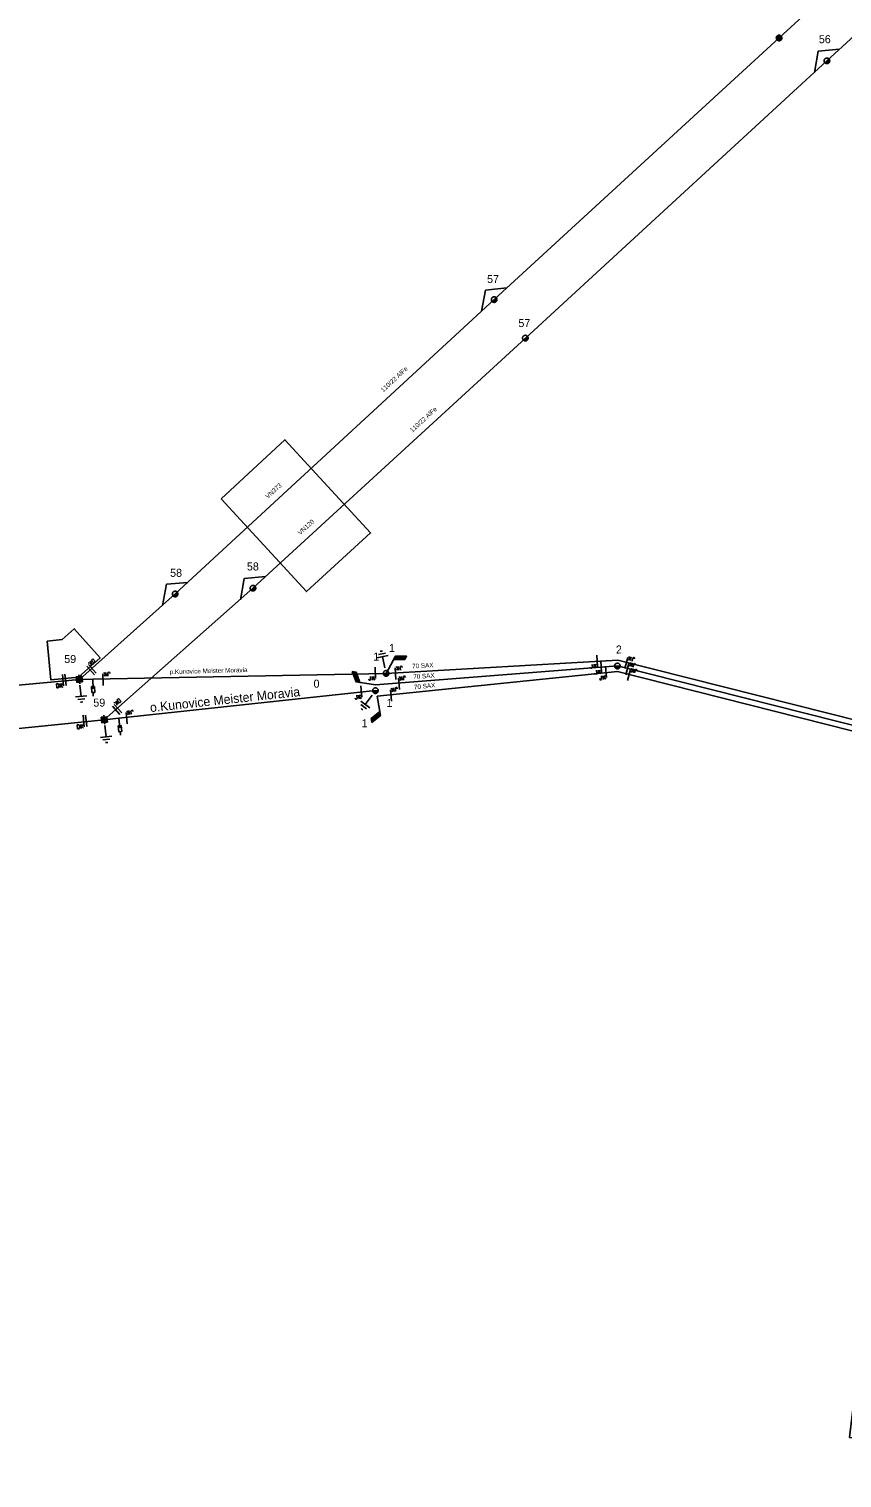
# Model space of a CAD drawing. Extents: x -540340 to -537226, y -1183949 to -1180375.
# Drawn here: x -539921.3 to -539743.5, y -1183378.3 to -1183061.3 of the extents above; entities that cross this region are included whole.
import ezdxf

# ---------------------------------------------------------------- set-up
doc = ezdxf.new("R2010")
doc.units = 0
for name, color, linetype in [('Default', 7, 'Continuous'), ('Vrstva 1', 7, 'Continuous'), ('Vrstva 11', 7, 'Continuous'), ('Vrstva 12', 7, 'Continuous'), ('Vrstva 13', 7, 'Continuous'), ('Vrstva 14', 7, 'Continuous'), ('Vrstva 15', 7, 'Continuous'), ('Vrstva 16', 7, 'Continuous'), ('Vrstva 18', 7, 'Continuous'), ('Vrstva 2', 7, 'Continuous'), ('Vrstva 3', 7, 'Continuous'), ('Vrstva 35', 7, 'Continuous'), ('Vrstva 4', 7, 'Continuous'), ('Vrstva 52', 7, 'Continuous'), ('Vrstva 54', 7, 'Continuous'), ('Vrstva 57', 7, 'Continuous'), ('Vrstva 59', 7, 'Continuous')]:
    doc.layers.add(name, color=color, linetype=linetype)

# ---------------------------------------------------------------- blocks, each defined once
blk = doc.blocks.new('VN850')
at = {"layer": 'Vrstva 15'}
for points in [[(-0.56, 1.43), (-0.56, -1.07)], [(-0.01, 1.43), (-0.01, -1.07)], [(-2.09, -0.54), (-1.78, -0.54)], [(-2.09, -1.41), (-2.09, -0.54)], [(-1.78, -1.41), (-2.09, -1.41)], [(-1.78, -0.54), (-1.66, -0.6)], [(-1.67, -1.35), (-1.78, -1.41)], [(-1.59, -1.2), (-1.67, -1.35)], [(-1.66, -0.6), (-1.59, -0.75)], [(-1.59, -0.75), (-1.55, -0.96)], [(-1.55, -0.96), (-1.59, -1.2)], [(-1.26, -0.54), (-1.26, -1.41)], [(-0.85, -0.54), (-1.26, -1.09)], [(-1.13, -0.92), (-0.77, -1.41)]]:
    blk.add_lwpolyline(points, dxfattribs=at)
blk = doc.blocks.new('VN840')
at = {"layer": 'Vrstva 15'}
for points in [[(-0.01, 1.41), (-0.01, -1.09)], [(-1.51, -1.24), (-1.51, -1.15)], [(-1.48, -1.35), (-1.51, -1.24)], [(-1.33, -1.42), (-1.48, -1.35)], [(-1.27, -1.42), (-1.33, -1.42)], [(-1.13, -1.35), (-1.27, -1.42)], [(-1.09, -1.24), (-1.13, -1.35)], [(-1.09, -0.59), (-1.09, -1.24)], [(-0.68, -0.59), (-0.68, -1.42)], [(-0.68, -1.11), (-0.27, -0.59)], [(-0.54, -0.94), (-0.2, -1.42)]]:
    blk.add_lwpolyline(points, dxfattribs=at)
blk = doc.blocks.new('VN860')
at = {"layer": 'Vrstva 15'}
for points in [[(-3.74, 0), (0.01, 2.82)], [(0.01, 2.82), (3.76, 0)]]:
    blk.add_lwpolyline(points, dxfattribs=at)
blk = doc.blocks.new('VN440')
at = {"layer": 'Vrstva 2'}
for points in [[(1.22, 0), (1.21, 0.13), (1.19, 0.25), (1.16, 0.38), (1.11, 0.5), (1.05, 0.61), (0.98, 0.72), (0.9, 0.82), (0.81, 0.91), (0.71, 0.99), (0.6, 1.06), (0.49, 1.12), (0.37, 1.16), (0.25, 1.2), (0.12, 1.22), (-0.01, 1.22), (-0.14, 1.22), (-0.26, 1.2), (-0.39, 1.16), (-0.51, 1.12), (-0.62, 1.06), (-0.73, 0.99), (-0.83, 0.91), (-0.92, 0.82), (-1, 0.72), (-1.07, 0.61), (-1.13, 0.5), (-1.18, 0.38), (-1.21, 0.25), (-1.23, 0.13), (-1.24, 0), (-1.23, -0.13), (-1.21, -0.26), (-1.18, -0.38), (-1.13, -0.5), (-1.07, -0.62), (-1, -0.73), (-0.92, -0.83), (-0.83, -0.92), (-0.73, -1), (-0.62, -1.07), (-0.51, -1.13), (-0.39, -1.17), (-0.26, -1.2), (-0.14, -1.23), (-0.01, -1.23), (0.12, -1.23), (0.25, -1.2), (0.37, -1.17), (0.49, -1.13), (0.6, -1.07), (0.71, -1), (0.81, -0.92), (0.9, -0.83), (0.98, -0.73), (1.05, -0.62), (1.11, -0.5), (1.16, -0.38), (1.19, -0.26), (1.21, -0.13), (1.22, 0)], [(-1.24, 0), (1.22, 0)], [(-1.18, -0.34), (1.1, -0.34)], [(-1.01, -0.63), (0.97, -0.63)], [(-0.74, -0.92), (0.68, -0.92)]]:
    blk.add_lwpolyline(points, dxfattribs=at)
blk = doc.blocks.new('VN820')
at = {"layer": 'Vrstva 13'}
for points in [[(0, 0), (0, -2.1)], [(-0.32, -1.63), (0.34, -1.63)], [(-0.32, -2.95), (-0.32, -1.63)], [(0.34, -2.95), (-0.32, -2.95)], [(0, -2.1), (-0.12, -1.86)], [(0, -2.1), (0.12, -1.86)], [(0, -2.95), (0, -3.75)], [(0.34, -1.63), (0.34, -2.95)]]:
    blk.add_lwpolyline(points, dxfattribs=at)
blk = doc.blocks.new('VN810')
at = {"layer": 'Vrstva 14'}
for points in [[(0, -1.25), (0, -3.75)], [(1.25, -3.75), (-1.25, -3.75)], [(0.77, -4.37), (-0.8, -4.37)], [(0, -5), (-0.25, -5)], [(0.27, -5), (0, -5)]]:
    blk.add_lwpolyline(points, dxfattribs=at)
blk = doc.blocks.new('VN001')
at = {"layer": 'Default'}
for p, q in [((1.82, 3.18), (4.23, 3.18)), ((1.85, 3.23), (4.26, 3.23)), ((1.87, 3.28), (4.29, 3.28)), ((1.9, 3.33), (4.32, 3.33)), ((1.93, 3.38), (4.35, 3.38)), ((1.96, 3.43), (4.37, 3.43)), ((1.99, 3.48), (4.4, 3.48)), ((2.02, 3.53), (4.43, 3.53)), ((2.05, 3.58), (4.46, 3.58)), ((2.07, 3.63), (4.49, 3.63)), ((2.1, 3.68), (4.52, 3.68)), ((2.13, 3.73), (2.54, 3.73)), ((1.73, 3.03), (4.14, 3.03)), ((1.76, 3.08), (4.17, 3.08)), ((1.79, 3.13), (4.2, 3.13))]:
    blk.add_line(p, q, dxfattribs=at)
blk.add_lwpolyline([(2.13, 3.73), (0, 0)], dxfattribs=at)
blk.add_lwpolyline([(4.55, 3.73), (2.13, 3.73), (1.7, 2.98), (4.12, 2.99)], close=True, dxfattribs=at)
blk = doc.blocks.new('VN460')
at = {"layer": 'Vrstva 2'}
for points in [[(1.23, 0), (1.22, 0.13), (1.2, 0.26), (1.17, 0.38), (1.12, 0.5), (1.06, 0.61), (0.99, 0.72), (0.91, 0.82), (0.82, 0.91), (0.72, 0.99), (0.61, 1.06), (0.5, 1.12), (0.38, 1.17), (0.26, 1.2), (0.13, 1.22), (0, 1.23), (-0.13, 1.22), (-0.26, 1.2), (-0.38, 1.17), (-0.5, 1.12), (-0.61, 1.06), (-0.72, 0.99), (-0.82, 0.91), (-0.91, 0.82), (-0.99, 0.72), (-1.06, 0.61), (-1.12, 0.5), (-1.17, 0.38), (-1.2, 0.26), (-1.22, 0.13), (-1.23, 0), (-1.22, -0.13), (-1.2, -0.26), (-1.17, -0.38), (-1.12, -0.5), (-1.06, -0.61), (-0.99, -0.72), (-0.91, -0.82), (-0.82, -0.91), (-0.72, -0.99), (-0.61, -1.06), (-0.5, -1.12), (-0.38, -1.17), (-0.26, -1.2), (-0.13, -1.22), (0, -1.23), (0.13, -1.22), (0.26, -1.2), (0.38, -1.17), (0.5, -1.12), (0.61, -1.06), (0.72, -0.99), (0.82, -0.91), (0.91, -0.82), (0.99, -0.72), (1.06, -0.61), (1.12, -0.5), (1.17, -0.38), (1.2, -0.26), (1.22, -0.13), (1.23, 0)], [(0.92, 0), (0.92, 0.1), (0.9, 0.19), (0.88, 0.28), (0.84, 0.37), (0.8, 0.46), (0.75, 0.54), (0.68, 0.62), (0.62, 0.68), (0.54, 0.74), (0.46, 0.8), (0.37, 0.84), (0.28, 0.88), (0.19, 0.9), (0.1, 0.92), (0, 0.92), (-0.1, 0.92), (-0.19, 0.9), (-0.28, 0.88), (-0.37, 0.84), (-0.46, 0.8), (-0.54, 0.74), (-0.62, 0.68), (-0.68, 0.62), (-0.75, 0.54), (-0.8, 0.46), (-0.84, 0.37), (-0.88, 0.28), (-0.9, 0.19), (-0.92, 0.1), (-0.92, 0), (-0.92, -0.1), (-0.9, -0.19), (-0.88, -0.29), (-0.84, -0.38), (-0.8, -0.46), (-0.75, -0.54), (-0.68, -0.62), (-0.62, -0.69), (-0.54, -0.75), (-0.46, -0.8), (-0.37, -0.84), (-0.28, -0.88), (-0.19, -0.9), (-0.1, -0.92), (0, -0.92), (0.1, -0.92), (0.19, -0.9), (0.28, -0.88), (0.37, -0.84), (0.46, -0.8), (0.54, -0.75), (0.62, -0.69), (0.68, -0.62), (0.75, -0.54), (0.8, -0.46), (0.84, -0.38), (0.88, -0.29), (0.9, -0.19), (0.92, -0.1), (0.92, 0)], [(0.61, 0), (0.61, 0.06), (0.6, 0.13), (0.58, 0.19), (0.56, 0.25), (0.53, 0.31), (0.5, 0.36), (0.46, 0.41), (0.41, 0.46), (0.36, 0.5), (0.31, 0.53), (0.25, 0.56), (0.19, 0.58), (0.13, 0.6), (0.06, 0.61), (0, 0.61), (-0.06, 0.61), (-0.13, 0.6), (-0.19, 0.58), (-0.25, 0.56), (-0.31, 0.53), (-0.36, 0.5), (-0.41, 0.46), (-0.46, 0.41), (-0.5, 0.36), (-0.53, 0.31), (-0.56, 0.25), (-0.58, 0.19), (-0.6, 0.13), (-0.61, 0.06), (-0.61, 0), (-0.61, -0.07), (-0.6, -0.13), (-0.58, -0.19), (-0.56, -0.25), (-0.53, -0.31), (-0.5, -0.36), (-0.46, -0.41), (-0.41, -0.46), (-0.36, -0.5), (-0.31, -0.53), (-0.25, -0.56), (-0.19, -0.58), (-0.13, -0.6), (-0.06, -0.61), (0, -0.61), (0.06, -0.61), (0.13, -0.6), (0.19, -0.58), (0.25, -0.56), (0.31, -0.53), (0.36, -0.5), (0.41, -0.46), (0.46, -0.41), (0.5, -0.36), (0.53, -0.31), (0.56, -0.25), (0.58, -0.19), (0.6, -0.13), (0.61, -0.06), (0.61, 0)], [(0.31, 0), (0.31, 0.03), (0.3, 0.06), (0.29, 0.09), (0.28, 0.12), (0.27, 0.15), (0.25, 0.18), (0.23, 0.21), (0.21, 0.23), (0.18, 0.25), (0.15, 0.27), (0.12, 0.28), (0.09, 0.29), (0.06, 0.3), (0.03, 0.31), (0, 0.31), (-0.03, 0.31), (-0.06, 0.3), (-0.09, 0.29), (-0.12, 0.28), (-0.15, 0.27), (-0.18, 0.25), (-0.21, 0.23), (-0.23, 0.21), (-0.25, 0.18), (-0.27, 0.15), (-0.28, 0.12), (-0.29, 0.09), (-0.3, 0.06), (-0.31, 0.03), (-0.31, 0), (-0.31, -0.03), (-0.3, -0.06), (-0.29, -0.1), (-0.28, -0.13), (-0.27, -0.15), (-0.25, -0.18), (-0.23, -0.21), (-0.21, -0.23), (-0.18, -0.25), (-0.15, -0.27), (-0.12, -0.28), (-0.09, -0.29), (-0.06, -0.3), (-0.03, -0.31), (0, -0.31), (0.03, -0.31), (0.06, -0.3), (0.09, -0.29), (0.12, -0.28), (0.15, -0.27), (0.18, -0.25), (0.21, -0.23), (0.23, -0.21), (0.25, -0.18), (0.27, -0.15), (0.28, -0.13), (0.29, -0.1), (0.3, -0.06), (0.31, -0.03), (0.31, 0)]]:
    blk.add_lwpolyline(points, dxfattribs=at)
blk = doc.blocks.new('VN470')
at = {"layer": 'Vrstva 2'}
for points in [[(-1.23, 1.22), (1.23, 1.22)], [(-1.23, -1.23), (-1.23, 1.22)], [(-0.92, 0.9), (0.92, 0.9)], [(-0.92, -0.95), (-0.92, 0.9)], [(-0.61, 0.61), (0.61, 0.61)], [(-0.61, -0.62), (-0.61, 0.61)], [(-0.31, -0.27), (-0.31, 0.34)], [(-0.31, 0.34), (0.31, 0.34)], [(0, 1.22), (0, 1.97)], [(0.31, 0.34), (0.31, -0.27)], [(0.61, 0.61), (0.61, -0.62)], [(0.92, 0.9), (0.92, -0.95)], [(1.23, 1.22), (1.23, -1.23)], [(1.23, -1.23), (-1.23, -1.23)], [(0.92, -0.95), (-0.92, -0.95)], [(0.61, -0.62), (-0.61, -0.62)], [(0.31, -0.27), (-0.31, -0.27)], [(0, -1.23), (0, -1.98)]]:
    blk.add_lwpolyline(points, dxfattribs=at)

msp = doc.modelspace()

# ---------------------------------------------------------------- linework, layer by layer
at = {"layer": 'Vrstva 1'}
for points in [[(-538750.53, -1181681.2), (-538749.33, -1181712.71), (-538744.97, -1181817.24), (-538743.58, -1181895.5), (-538773.54, -1181977.77), (-538805.22, -1182060.54), (-538837.47, -1182145.44), (-538866.82, -1182220.96), (-538895.79, -1182296.47), (-538969.65, -1182362.9), (-539051.89, -1182437.77), (-539124.04, -1182501.28), (-539198.82, -1182569.8), (-539277.47, -1182640.72), (-539357.09, -1182713.05), (-539436.34, -1182785.46), (-539516.79, -1182858.47), (-539596.04, -1182930.58), (-539682.18, -1183009.05), (-539746.81, -1183068.3), (-539812.77, -1183128.96), (-539872.34, -1183183.66), (-539904.86, -1183212.44)], [(-539910.31, -1183203.61), (-539889.36, -1183184.93), (-539819.58, -1183120.53), (-539757.27, -1183063.3), (-539687.65, -1182999.5), (-539602.47, -1182922.15), (-539522.85, -1182849.96), (-539443.45, -1182777.85), (-539363.3, -1182704.92), (-539283.21, -1182632.72)], [(-540012.36, -1183354.43), (-540009.96, -1183294.39), (-539986.67, -1183210.74), (-539910.31, -1183203.61)], [(-539904.86, -1183212.44), (-539980.4, -1183220.14), (-540003.99, -1183302.87), (-540008.15, -1183354.48)]]:
    msp.add_lwpolyline(points, dxfattribs=at)
at = {"layer": 'Vrstva 35'}
for points in [[(-539879.32, -1183164.09), (-539865.34, -1183151.2), (-539846.6, -1183171.57), (-539860.6, -1183184.42)], [(-539917.36, -1183195.23), (-539914.09, -1183194.92), (-539911.43, -1183192.55), (-539905.77, -1183198.89), (-539910.52, -1183203.13), (-539916.57, -1183203.69)]]:
    msp.add_lwpolyline(points, close=True, dxfattribs=at)
at = {"layer": 'Vrstva 4'}
for points in [[(-539843.22, -1183202.3), (-539792.51, -1183199.43), (-539723.81, -1183216.77), (-539658.93, -1183211.54), (-539583.06, -1183205.79)], [(-539910.31, -1183203.61), (-539907.36, -1183203.55), (-539843.22, -1183202.3)], [(-539845.55, -1183204.84), (-539792.63, -1183200.68), (-539723.91, -1183218), (-539734.07, -1183303.85), (-539741.84, -1183369.42), (-539668.89, -1183378.31)], [(-539845.19, -1183207.26), (-539792.58, -1183201.89), (-539724.05, -1183219.21), (-539658.75, -1183213.98), (-539582.95, -1183207.03)]]:
    msp.add_lwpolyline(points, dxfattribs=at)
at = {"layer": 'Vrstva 52'}
msp.add_lwpolyline([(-539904.86, -1183212.44), (-539901.69, -1183212.1), (-539845.55, -1183206.08)], dxfattribs=at)

# ---------------------------------------------------------------- block references
at = {"layer": 'Vrstva 11'}
for p, rotation in [((-539843.22, -1183202.3), 1.0974722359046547), ((-539845.55, -1183204.84), 110.73362780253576), ((-539845.19, -1183207.26), -140.40446383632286)]:
    msp.add_blockref('VN001', p, dxfattribs=dict(at, rotation=rotation))
at = {"layer": 'Vrstva 13'}
for name, p, xscale, yscale, rotation in [('VN460', (-539757.27, -1183063.31), 0.5, 0.5, 42.69776945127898), ('VN440', (-539746.81, -1183068.3), 0.5000000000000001, 0.5, 42.312650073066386), ('VN440', (-539819.58, -1183120.53), 0.5, 0.5, 42.39974992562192), ('VN440', (-539812.77, -1183128.96), 0.5, 0.5, 42.35340004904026), ('VN440', (-539889.36, -1183184.93), 0.5, 0.5, 41.722772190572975), ('VN440', (-539872.34, -1183183.66), 0.5, 0.5, 41.44218061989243), ('VN440', (-539792.63, -1183200.68), 0.5000000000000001, 0.5000000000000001, 1.8341054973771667), ('VN470', (-539910.31, -1183203.61), 0.49999999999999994, 0.5000000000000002, 5.629222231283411), ('VN440', (-539843.22, -1183202.3), 0.5000000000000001, 0.5, 1.0974722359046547), ('VN440', (-539845.55, -1183206.08), 0.4999999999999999, 0.49999999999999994, 5.99906389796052), ('VN470', (-539904.86, -1183212.45), 0.5000000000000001, 0.5, 5.814858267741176)]:
    msp.add_blockref(name, p, dxfattribs=dict(at, xscale=xscale, yscale=yscale, rotation=rotation))
at = {"layer": 'Vrstva 15'}
for p, rotation in [((-539843.22, -1183202.3), -168.0209639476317), ((-539910.31, -1183203.61), 5.629222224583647), ((-539845.55, -1183206.08), -36.26562504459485), ((-539904.86, -1183212.44), 5.814858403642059)]:
    msp.add_blockref('VN810', p, dxfattribs=dict(at, rotation=rotation))
at = {"layer": 'Vrstva 16'}
for p, rotation in [((-539907.36, -1183203.55), 1.5765195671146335), ((-539901.69, -1183212.1), 5.958369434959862)]:
    msp.add_blockref('VN820', p, dxfattribs=dict(at, rotation=rotation))
at = {"layer": 'Vrstva 18'}
for name, p, rotation in [('VN860', (-539746.81, -1183068.3), 42.64404726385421), ('VN860', (-539819.58, -1183120.53), 42.39938056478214), ('VN860', (-539889.36, -1183184.93), 41.721525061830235), ('VN860', (-539872.34, -1183183.66), 42.35320559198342), ('VN850', (-539907.99, -1183201.54), -138.27847493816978), ('VN840', (-539797.07, -1183199.69), 3.2417193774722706), ('VN840', (-539796.17, -1183200.96), 4.498130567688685), ('VN840', (-539790.64, -1183199.9), 165.83040279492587), ('VN840', (-539790.43, -1183201.23), 165.8547332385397), ('VN850', (-539913.31, -1183203.89), 5.337066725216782), ('VN840', (-539905.14, -1183203.51), -178.88356102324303), ('VN840', (-539845.56, -1183202.35), 1.5766528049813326), ('VN840', (-539841.17, -1183202.21), -177.45153336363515), ('VN840', (-539840.43, -1183204.44), -175.50186943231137), ('VN840', (-539795.12, -1183202.15), 5.827133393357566), ('VN840', (-539790.08, -1183202.52), 165.8130583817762), ('VN840', (-539848.61, -1183206.4), 5.958341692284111), ('VN840', (-539842.16, -1183206.95), -174.17286673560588), ('VN850', (-539902.38, -1183210.25), -138.5581694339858), ('VN850', (-539908.79, -1183212.84), 5.815036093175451), ('VN840', (-539899.98, -1183211.92), -173.87483891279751)]:
    msp.add_blockref(name, p, dxfattribs=dict(at, rotation=rotation))

# ---------------------------------------------------------------- texts
at = {"layer": 'Vrstva 12'}
for s, p in [('1', (-539842.59, -1183197.6)), ('0', (-539859.09, -1183205.43)), ('1', (-539848.58, -1183214.09))]:
    msp.add_text(s, height=1.75, dxfattribs=at).set_placement(p)
at = {"layer": 'Vrstva 14'}
for s, p in [('56', (-539748.58, -1183064.45)), ('57', (-539821.14, -1183116.91)), ('57', (-539814.29, -1183126.55)), ('58', (-539873.66, -1183179.79)), ('58', (-539890.46, -1183181.18)), ('59', (-539913.62, -1183200.03)), ('1', (-539846.03, -1183199.52)), ('59', (-539907.26, -1183209.57)), ('1', (-539843.13, -1183209.62))]:
    msp.add_text(s, height=1.75, dxfattribs=at).set_placement(p)
msp.add_text('2', height=1.75, rotation=1.834, dxfattribs=at).set_placement((-539792.93, -1183197.97))
at = {"layer": 'Vrstva 2'}
for rotation, p in [(42.704, (-539843.85, -1183140.86)), (42.559, (-539837.47, -1183149.66))]:
    msp.add_text('110/22 AlFe', height=1, rotation=rotation, dxfattribs=at).set_placement(p)
at = {"layer": 'Vrstva 3'}
for s, rotation, p in [('VN373', 42.704, (-539869.05, -1183164.16)), ('VN120', 42.559, (-539861.97, -1183172.1))]:
    msp.add_text(s, height=1, rotation=rotation, dxfattribs=at).set_placement(p)
at = {"layer": 'Vrstva 54'}
msp.add_text('o.Kunovice Meister Moravia', height=2, rotation=6.125, dxfattribs=at).set_placement((-539894.76, -1183210.78))
at = {"layer": 'Vrstva 57'}
for rotation, p in [(3.242, (-539837.51, -1183201.22)), (4.498, (-539837.25, -1183203.57)), (5.826, (-539837.08, -1183205.82))]:
    msp.add_text('70 SAX', height=1, rotation=rotation, dxfattribs=at).set_placement(p)
at = {"layer": 'Vrstva 59'}
msp.add_text('p.Kunovice Meister Moravia', height=1, rotation=1.577, dxfattribs=at).set_placement((-539890.55, -1183202.47))

doc.saveas('drawing.dxf')
